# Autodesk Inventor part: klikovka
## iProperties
Shininess: 64.0
Length Units: 11269
Angle Units: 11279
Time Units: 11290
Mass Units: 11283
Length Display Precision: 3
Angle Display Precision: 2
Compacted: True
Part Number: klikovka
Document SubType Name: Modeling
Created: 2003-06
Material: Výchozí
Density: 0.0
Volumn: 0.0
Area: 0.0
PropertySet Name: Model Information
Control State: 0
Master: False
Checked Out: False
Title: Klikovka
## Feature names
1. Vysunutí1 [Extrusion]
2. Vysunutí2 [Extrusion]
3. Vysunutí3 [Extrusion]
4. Vysunutí4 [Extrusion]
5. Vysunutí5 [Extrusion]
